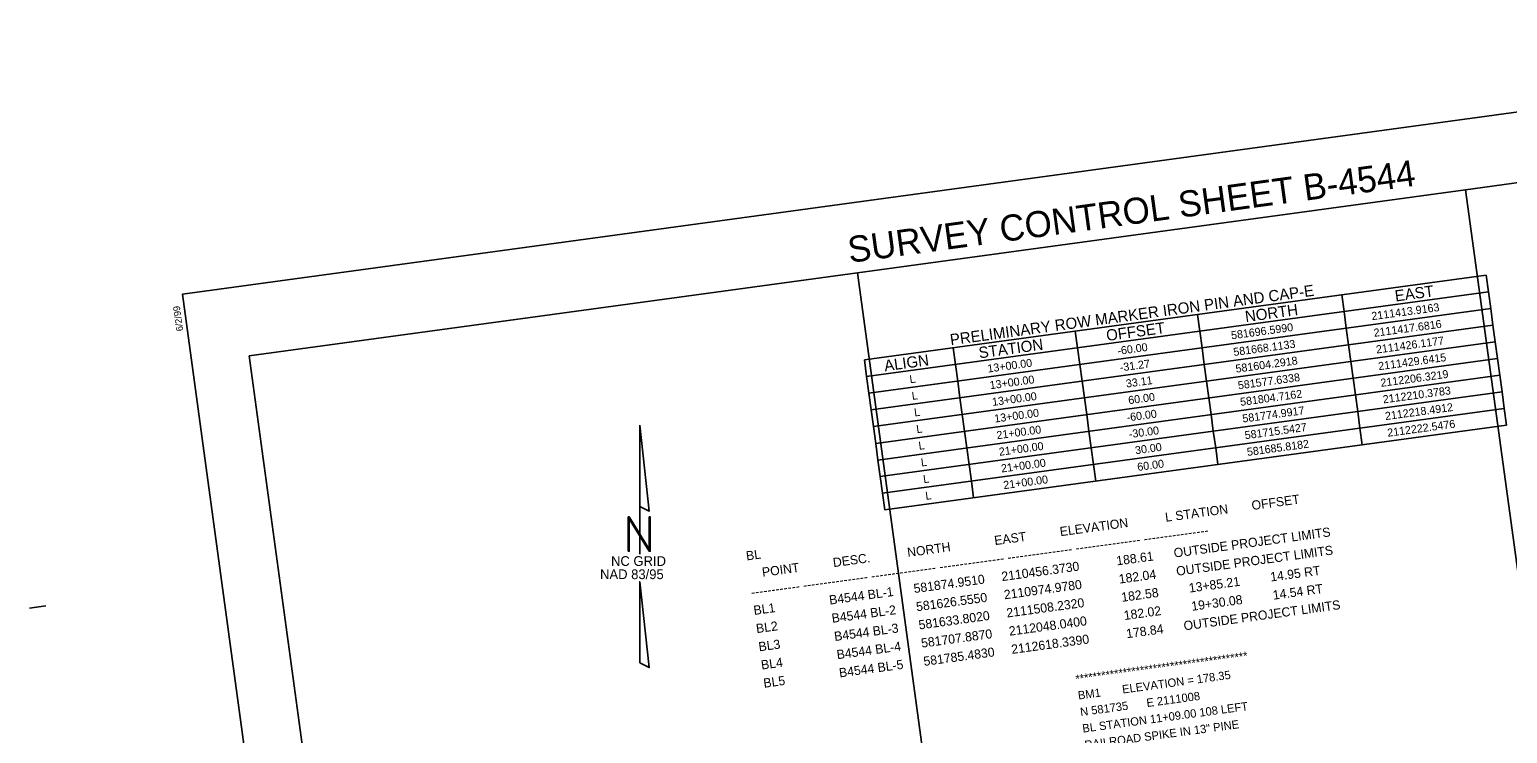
# Model space of a CAD drawing. Extents: x 2110924 to 2112563, y 581169 to 582406.
# Drawn here: x 2110924 to 2111987, y 581874 to 582381 of the extents above; entities that cross this region are included whole.
import ezdxf

# ---------------------------------------------------------------- set-up
doc = ezdxf.new("R2010")
doc.units = 0
for name, color, linetype in [('CTL North Arrow NAD 83 95 CELL', 7, 'Continuous'), ('CTL Sheet Border CELL', 7, 'Continuous'), ('CTL Sheet Notes CELL', 7, 'Continuous'), ('CTL Sheet Table Cell', 7, 'Continuous'), ('CTL Sheet Text', 7, 'Continuous'), ('Scratch_Level_3', 7, 'Continuous')]:
    doc.layers.add(name, color=color, linetype=linetype)

msp = doc.modelspace()

# ---------------------------------------------------------------- linework, layer by layer
at = {"layer": 'CTL North Arrow NAD 83 95 CELL'}
for points in [[(2111363, 582095.9), (2111363, 582037.5), (2111369.9, 582034.1)], [(2111354.8, 582005.3), (2111355.5, 582005.3), (2111355.5, 582028.6), (2111369.9, 582005.3), (2111370.6, 582005.3), (2111370.6, 582030), (2111369.9, 582030), (2111369.9, 582006.7), (2111355.5, 582030), (2111354.8, 582030)], [(2111363, 581925), (2111369.9, 581921.6), (2111363, 581983.3)]]:
    msp.add_lwpolyline(points, close=True, dxfattribs=at)
msp.add_lwpolyline([(2111363, 582037.5), (2111363, 582003.2)], dxfattribs=at)
at = {"layer": 'CTL Sheet Border CELL'}
msp.add_line((2110923.9, 581964.3), (2110935.6, 581965.9), dxfattribs=at)
msp.add_lwpolyline([(2112429.6, 582380.6), (2111033.9, 582190.2), (2111167.2, 581213.1), (2112563, 581403.6)], close=True, dxfattribs=at)
at = {"layer": 'CTL Sheet Table Cell'}
for p, q in [((2111524.7, 582142.9), (2111972.1, 582203.9)), ((2111972.1, 582203.9), (2111973.8, 582191.9)), ((2111526.3, 582130.9), (2111973.8, 582191.9)), ((2111868.3, 582189.7), (2111869.9, 582177.8)), ((2111973.8, 582191.9), (2111975.4, 582179.9)), ((2111528, 582118.9), (2111975.4, 582179.9)), ((2111869.9, 582177.8), (2111871.5, 582165.8)), ((2111975.4, 582179.9), (2111977, 582168)), ((2111529.6, 582106.9), (2111977, 582168)), ((2111764.4, 582175.6), (2111766, 582163.6)), ((2111871.5, 582165.8), (2111873.2, 582153.8)), ((2111977, 582168), (2111978.7, 582156)), ((2111531.2, 582094.9), (2111978.7, 582156)), ((2111676.5, 582163.6), (2111678.1, 582151.6)), ((2111766, 582163.6), (2111767.7, 582151.6)), ((2111978.7, 582156), (2111980.3, 582144)), ((2111532.9, 582082.9), (2111980.3, 582144)), ((2111588.6, 582151.6), (2111590.2, 582139.6)), ((2111678.1, 582151.6), (2111679.8, 582139.6)), ((2111767.7, 582151.6), (2111769.3, 582139.6)), ((2111873.2, 582153.8), (2111874.8, 582141.8)), ((2111980.3, 582144), (2111981.9, 582132)), ((2111524.7, 582142.9), (2111526.3, 582130.9)), ((2111590.2, 582139.6), (2111591.9, 582127.6)), ((2111679.8, 582139.6), (2111681.4, 582127.6)), ((2111769.3, 582139.6), (2111770.9, 582127.6)), ((2111874.8, 582141.8), (2111876.4, 582129.8)), ((2111526.3, 582130.9), (2111528, 582118.9)), ((2111534.5, 582070.9), (2111981.9, 582132)), ((2111591.9, 582127.6), (2111593.5, 582115.6)), ((2111681.4, 582127.6), (2111683, 582115.6)), ((2111770.9, 582127.6), (2111772.6, 582115.6)), ((2111876.4, 582129.8), (2111878.1, 582117.8)), ((2111981.9, 582132), (2111983.6, 582120)), ((2111528, 582118.9), (2111529.6, 582106.9)), ((2111536.1, 582059), (2111983.6, 582120)), ((2111593.5, 582115.6), (2111595.1, 582103.6)), ((2111683, 582115.6), (2111684.7, 582103.6)), ((2111772.6, 582115.6), (2111774.2, 582103.7)), ((2111878.1, 582117.8), (2111879.7, 582105.8)), ((2111983.6, 582120), (2111985.2, 582108)), ((2111529.6, 582106.9), (2111531.2, 582094.9)), ((2111537.8, 582047), (2111985.2, 582108)), ((2111595.1, 582103.6), (2111596.8, 582091.7)), ((2111684.7, 582103.6), (2111686.3, 582091.7)), ((2111774.2, 582103.7), (2111775.8, 582091.7)), ((2111879.7, 582105.8), (2111881.3, 582093.9)), ((2111985.2, 582108), (2111986.8, 582096)), ((2111531.2, 582094.9), (2111532.9, 582082.9)), ((2111539.4, 582035), (2111986.8, 582096)), ((2111596.8, 582091.7), (2111598.4, 582079.7)), ((2111686.3, 582091.7), (2111687.9, 582079.7)), ((2111775.8, 582091.7), (2111777.5, 582079.7)), ((2111881.3, 582093.9), (2111883, 582081.9)), ((2111532.9, 582082.9), (2111534.5, 582070.9)), ((2111534.5, 582070.9), (2111536.1, 582059)), ((2111598.4, 582079.7), (2111600.1, 582067.7)), ((2111687.9, 582079.7), (2111689.6, 582067.7)), ((2111777.5, 582079.7), (2111779.1, 582067.7)), ((2111536.1, 582059), (2111537.8, 582047)), ((2111600.1, 582067.7), (2111601.7, 582055.7)), ((2111689.6, 582067.7), (2111691.2, 582055.7)), ((2111601.7, 582055.7), (2111603.3, 582043.7)), ((2111537.8, 582047), (2111539.4, 582035))]:
    msp.add_line(p, q, dxfattribs=at)
at = {"layer": 'Scratch_Level_3'}
for p, q in [((2111957.4, 582265.4), (2112395.1, 582325.1)), ((2111519.7, 582205.7), (2111957.4, 582265.4)), ((2111957.4, 582265.4), (2112055.8, 581544.5)), ((2111082, 582145.9), (2111519.7, 582205.7)), ((2111519.7, 582205.7), (2111618.1, 581484.8)), ((2111082, 582145.9), (2111180.4, 581425))]:
    msp.add_line(p, q, dxfattribs=at)

# ---------------------------------------------------------------- texts
at = {"layer": 'CTL North Arrow NAD 83 95 CELL'}
for s, p in [('NC GRID', (2111342.4, 581994.7)), ('NAD 83/95', (2111334.5, 581985.2))]:
    msp.add_text(s, height=7, dxfattribs=at).set_placement(p)
at = {"layer": 'CTL Sheet Border CELL'}
for s, height, rotation, p in [('SURVEY CONTROL SHEET B-4544', 18.783, 7.771, (2111514.1, 582212.7)), ('6/2/99', 4.93, 97.771, (2111034.5, 582163.9))]:
    msp.add_text(s, height=height, rotation=rotation, dxfattribs=at).set_placement(p)
at = {"layer": 'CTL Sheet Notes CELL'}
for s, height, p in [('PRELIMINARY ROW MARKER IRON PIN AND CAP-E', 8.064, (2111586.9, 582153.4)), ('EAST', 8.06, (2111907, 582184.9)), ('NORTH', 8.06, (2111799.2, 582170.1)), ('OFFSET', 8.06, (2111699.3, 582156.5)), ('STATION', 8.06, (2111607.5, 582144)), ('ALIGN', 8.06, (2111539.5, 582134.7))]:
    msp.add_text(s, height=height, rotation=7.771, dxfattribs=at).set_placement(p)
at = {"layer": 'CTL Sheet Text'}
for s, height, p in [('2111413.9163', 5.76, (2111890, 582171.5)), ('581696.5990', 5.76, (2111789, 582157.7)), ('2111417.6816', 5.76, (2111891.6, 582159.5)), ('-60.00', 5.76, (2111707.2, 582146.5)), ('581668.1133', 5.76, (2111790.6, 582145.7)), ('2111426.1177', 5.76, (2111893.3, 582147.5)), ('581604.2918', 5.76, (2111792.2, 582133.7)), ('2111429.6415', 5.76, (2111894.9, 582135.5)), ('13+00.00', 5.76, (2111613.7, 582133.8)), ('-31.27', 5.76, (2111708.9, 582134.6)), ('581577.6338', 5.76, (2111793.9, 582121.7)), ('2112206.3219', 5.76, (2111896.5, 582123.5)), ('L', 5.76, (2111557.6, 582126.1)), ('13+00.00', 5.76, (2111615.3, 582121.8)), ('33.11', 5.76, (2111713.3, 582123)), ('2112210.3783', 5.76, (2111898.2, 582111.6)), ('L', 5.76, (2111559.2, 582114.1)), ('13+00.00', 5.76, (2111617, 582109.8)), ('60.00', 5.76, (2111715, 582111)), ('581804.7162', 5.76, (2111795.5, 582109.8)), ('L', 5.76, (2111560.9, 582102.2)), ('13+00.00', 5.76, (2111618.6, 582097.8)), ('-60.00', 5.76, (2111713.8, 582098.6)), ('581774.9917', 5.76, (2111797.1, 582097.8)), ('2112218.4912', 5.76, (2111899.8, 582099.6)), ('L', 5.76, (2111562.5, 582090.2)), ('21+00.00', 5.76, (2111620.2, 582085.8)), ('-30.00', 5.76, (2111715.4, 582086.6)), ('581715.5427', 5.76, (2111798.8, 582085.8)), ('2112222.5476', 5.76, (2111901.4, 582087.6)), ('L', 5.76, (2111564.1, 582078.2)), ('21+00.00', 5.76, (2111621.9, 582073.9)), ('30.00', 5.76, (2111719.9, 582075)), ('581685.8182', 5.76, (2111800.4, 582073.8)), ('L', 5.76, (2111565.8, 582066.2)), ('21+00.00', 5.76, (2111623.5, 582061.9)), ('60.00', 5.76, (2111721.5, 582063)), ('L', 5.76, (2111567.4, 582054.2)), ('21+00.00', 5.76, (2111625.1, 582049.9)), ('    POINT          DESC.           NORTH             EAST          ELEVATION           L STATION       OFFSET', 6.6, (2111441.8, 581985.5)), ('L', 5.76, (2111569, 582042.2)), ('------------ ---------------- ---------------- ---------------- ---------------- ---------------- ----------------', 6.6, (2111443.6, 581972.4)), ('BL1                B4544 BL-1      581874.9510     2110456.3730           188.61      OUTSIDE PROJECT LIMITS                 ', 6.6, (2111445.4, 581959.4)), ('BL', 6.6, (2111440, 581998.6)), ('BL2                B4544 BL-2      581626.5550     2110974.9780           182.04      OUTSIDE PROJECT LIMITS                 ', 6.6, (2111447.2, 581946.3)), ('BL3                B4544 BL-3      581633.8020     2111508.2320           182.58         13+85.21         14.95 RT', 6.6, (2111449, 581933.2)), ('BL4                B4544 BL-4      581707.8870     2112048.0400           182.02         19+30.08         14.54 RT', 6.6, (2111450.8, 581920.1)), ('BL5                B4544 BL-5      581785.4830     2112618.3390           178.84      OUTSIDE PROJECT LIMITS                 ', 6.6, (2111452.5, 581907)), ('****************************************', 6, (2111677.1, 581910.3)), ('BM1       ELEVATION = 178.35', 6, (2111678.8, 581898.5)), ('N 581735      E 2111008', 6, (2111680.4, 581886.6)), ('BL STATION 11+09.00 108 LEFT', 6, (2111682, 581874.7)), ('RAILROAD SPIKE IN 13" PINE', 6, (2111683.6, 581862.8))]:
    msp.add_text(s, height=height, rotation=7.771, dxfattribs=at).set_placement(p)

doc.saveas('drawing.dxf')
